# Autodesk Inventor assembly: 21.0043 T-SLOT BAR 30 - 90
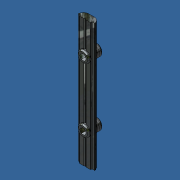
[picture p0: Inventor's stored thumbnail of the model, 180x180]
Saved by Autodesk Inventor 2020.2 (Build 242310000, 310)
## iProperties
Created: 2021-01
Part Number: 21.0043 T-SLOT BAR 30 - 90
Document SubType Name: Assembly
Designer: amoles
Author: amoles
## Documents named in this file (3)
- Y:\INVENTOR LIBRARIES\PARTS LIBRARY\30 SERIES\21.0043 T-SLOT BAR 30 - 90.iam
- Y:\INVENTOR LIBRARIES\PARTS LIBRARY\30 SERIES\SUBCOMPONENTS\21.0043_1 T-SLOT BAR 30 - 90 BAR.ipt
- Y:\INVENTOR LIBRARIES\PARTS LIBRARY\FASTENING ELEMENTS\SET SCREWS\21.1306 M8X10 SET SCREW.ipt
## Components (3 placed, 2 different names)
1. 21.0043_1 T-SLOT BAR 30 - 90 BAR:1 — Mate:1, Flush:1, Flush:2, Mate:2, Mate:3, Mate:4, Angle:1, Angle:2
2. 21.1306 M8x10 SET SCREW:1 — Flush:3, Mate:2, Mate:3, Angle:1
3. 21.1306 M8x10 SET SCREW:2 — Flush:3, Mate:4, Angle:2
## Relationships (9: Mate 4, Flush 3, Angle 2)
- Mate:1: 21.0043_1 T-SLOT BAR 30 - 90 BAR:1
- Flush:1: 21.0043_1 T-SLOT BAR 30 - 90 BAR:1
- Flush:2: 21.0043_1 T-SLOT BAR 30 - 90 BAR:1
- Flush:3: 21.1306 M8x10 SET SCREW:1 ↔ 21.1306 M8x10 SET SCREW:2
- Mate:2: 21.0043_1 T-SLOT BAR 30 - 90 BAR:1 ↔ 21.1306 M8x10 SET SCREW:1
- Mate:3: 21.0043_1 T-SLOT BAR 30 - 90 BAR:1 ↔ 21.1306 M8x10 SET SCREW:1
- Mate:4: 21.0043_1 T-SLOT BAR 30 - 90 BAR:1 ↔ 21.1306 M8x10 SET SCREW:2
- Angle:1: 21.0043_1 T-SLOT BAR 30 - 90 BAR:1 ↔ 21.1306 M8x10 SET SCREW:1
- Angle:2: 21.0043_1 T-SLOT BAR 30 - 90 BAR:1 ↔ 21.1306 M8x10 SET SCREW:2
